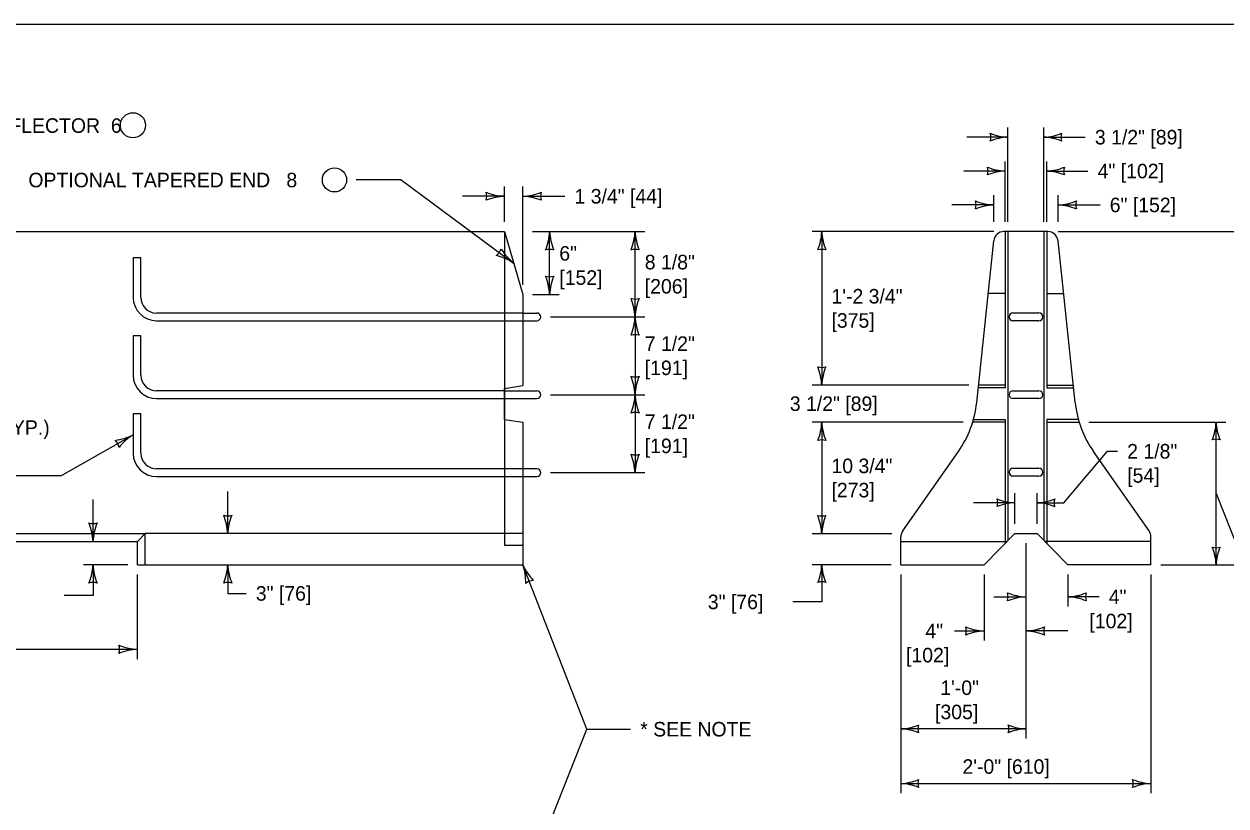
# Model space of a CAD drawing. Extents: x 49991.4 to 50021, y 49987.6 to 50011.4.
# Drawn here: x 50005.623 to 50010.586, y 49995.768 to 49998.999 of the extents above; entities that cross this region are included whole.
import ezdxf

# ---------------------------------------------------------------- set-up
doc = ezdxf.new("R2010")
doc.units = 0
for name, color, linetype in [('Level 1', 7, 'Continuous'), ('Level 2', 7, 'Continuous'), ('Level 3', 7, 'Continuous'), ('Level 4', 7, 'Continuous')]:
    doc.layers.add(name, color=color, linetype=linetype)

msp = doc.modelspace()

# ---------------------------------------------------------------- linework, layer by layer
at = {"layer": 'Level 1'}
for p, q in [((50002.518, 49998.1414), (50007.607, 49998.1414)), ((50007.607, 49998.1414), (50007.6828, 49997.8813)), ((50009.5572, 49997.4345), (50009.6279, 49998.1036)), ((50009.8515, 49998.1415), (50009.67, 49998.1415)), ((50009.6745, 49998.1415), (50009.6745, 49997.4963)), ((50009.686, 49998.1415), (50009.686, 49996.8645)), ((50009.8349, 49998.1415), (50009.8349, 49996.8645)), ((50009.8464, 49998.1415), (50009.8464, 49997.4963)), ((50009.9637, 49997.4345), (50009.893, 49998.1036)), ((50007.6828, 49997.8813), (50007.6829, 49997.5051)), ((50009.6745, 49997.8858), (50009.6049, 49997.8858)), ((50009.8464, 49997.8858), (50009.916, 49997.8858)), ((50007.6829, 49997.8049), (50007.7407, 49997.8049)), ((50009.7069, 49997.8052), (50009.8143, 49997.8052)), ((50007.6829, 49997.7728), (50007.7407, 49997.7728)), ((50009.8143, 49997.773), (50009.7069, 49997.773)), ((50007.6078, 49997.4932), (50007.6829, 49997.5051)), ((50009.6745, 49997.5069), (50009.5648, 49997.5069)), ((50009.8464, 49997.5069), (50009.9561, 49997.5069)), ((50007.6078, 49997.3655), (50007.6078, 49997.4932)), ((50007.6078, 49997.4833), (50007.7407, 49997.4833)), ((50009.6745, 49997.4963), (50009.5637, 49997.4963)), ((50009.7069, 49997.4835), (50009.8143, 49997.4835)), ((50009.8464, 49997.4963), (50009.9572, 49997.4963)), ((50007.6078, 49997.4512), (50007.7407, 49997.4512)), ((50009.8143, 49997.4513), (50009.7069, 49997.4513)), ((50007.6078, 49997.3655), (50007.6829, 49997.3535)), ((50009.544, 49997.3649), (50009.6745, 49997.3649)), ((50009.6745, 49997.3649), (50009.6745, 49996.8528)), ((50009.8464, 49997.3649), (50009.8464, 49996.8528)), ((50009.9769, 49997.3649), (50009.8464, 49997.3649)), ((50007.6829, 49997.3535), (50007.6829, 49996.7646)), ((50009.6745, 49997.3536), (50009.5407, 49997.3536)), ((50009.8464, 49997.3536), (50009.9802, 49997.3536)), ((50009.2517, 49996.9042), (50009.4814, 49997.232)), ((50010.2692, 49996.9042), (50010.0395, 49997.232)), ((50007.7408, 49997.1611), (50007.6829, 49997.161)), ((50009.7069, 49997.163), (50009.8143, 49997.163)), ((50007.6829, 49997.1289), (50007.7407, 49997.129)), ((50009.8143, 49997.1308), (50009.7069, 49997.1308)), ((50004.0777, 49996.8932), (50006.1232, 49996.8932)), ((50004.1097, 49996.8611), (50006.0912, 49996.8611)), ((50006.1232, 49996.8932), (50006.0912, 49996.8611)), ((50006.0912, 49996.7646), (50006.0912, 49996.8611)), ((50006.1232, 49996.7646), (50006.1232, 49996.8932)), ((50009.244, 49996.7646), (50009.244, 49996.8799)), ((50009.5877, 49996.7646), (50009.7144, 49996.8933)), ((50009.7144, 49996.8933), (50009.8065, 49996.8933)), ((50009.9332, 49996.7646), (50009.8065, 49996.8933)), ((50010.2769, 49996.7646), (50010.2769, 49996.8799)), ((50006.0912, 49996.7646), (50007.6829, 49996.7646)), ((50009.244, 49996.7646), (50009.5877, 49996.7646)), ((50010.2769, 49996.7646), (50009.9332, 49996.7646))]:
    msp.add_line(p, q, dxfattribs=at)
msp.add_lwpolyline([(49999.3835, 49998.9992), (50016.7501, 49998.9992), (50016.7501, 49987.7988), (49999.3835, 49987.7988)], close=True, dxfattribs=at)
for centre, radius, start, end in [((50009.67, 49998.0991), 0.0423, 90, 173.9725), ((50009.8509, 49998.0991), 0.0423, 6.0275, 90), ((50007.7407, 49997.7888), 0.0161, 270, 90), ((50009.7069, 49997.7891), 0.0161, 90, 270), ((50009.8143, 49997.7891), 0.0161, 270, 90), ((50007.7407, 49997.4673), 0.0161, 270, 90), ((50009.7069, 49997.4674), 0.0161, 90, 270), ((50009.8143, 49997.4674), 0.0161, 270, 90), ((50009.1277, 49997.4798), 0.4318, 324.9777, 353.9725), ((50010.3932, 49997.4798), 0.4318, 186.0275, 215.0223), ((50007.7407, 49997.1451), 0.0161, 270.1368, 89.5016), ((50009.7069, 49997.1469), 0.0161, 90, 270), ((50009.8143, 49997.1469), 0.0161, 270, 90), ((50009.2863, 49996.8799), 0.0423, 144.9777, 180), ((50010.2346, 49996.8799), 0.0423, 0, 35.0223)]:
    msp.add_arc(centre, radius, start, end, dxfattribs=at)
at = {"layer": 'Level 2'}
for centre, radius in [((50006.0727, 49998.5808), 0.052), ((50006.905, 49998.355), 0.05)]:
    msp.add_circle(centre, radius, dxfattribs=at)
at = {"layer": 'Level 3'}
for p, q in [((50009.686, 49998.1815), (50009.686, 49998.5716)), ((50009.8349, 49998.1815), (50009.8349, 49998.5716)), ((50009.686, 49998.5316), (50009.5157, 49998.5316)), ((50009.8349, 49998.5316), (50010.0052, 49998.5316)), ((50009.6745, 49998.1815), (50009.6745, 49998.4316)), ((50009.8464, 49998.1815), (50009.8464, 49998.4316)), ((50007.1798, 49998.355), (50006.995, 49998.355)), ((50007.1798, 49998.355), (50007.6449, 49998.0114)), ((50009.6745, 49998.3916), (50009.5042, 49998.3916)), ((50009.8464, 49998.3916), (50010.0167, 49998.3916)), ((50007.607, 49998.1814), (50007.607, 49998.3274)), ((50007.6828, 49997.9213), (50007.6828, 49998.3274)), ((50007.607, 49998.2874), (50007.4336, 49998.2874)), ((50007.6828, 49998.2874), (50007.8563, 49998.2874)), ((50009.6279, 49998.2516), (50009.4544, 49998.2516)), ((50009.6279, 49998.1815), (50009.6279, 49998.2916)), ((50009.893, 49998.1815), (50009.893, 49998.2916)), ((50009.893, 49998.2516), (50010.0665, 49998.2516)), ((50007.7228, 49998.1414), (50008.1864, 49998.1414)), ((50007.7934, 49997.8813), (50007.7934, 49998.1414)), ((50008.1464, 49997.7888), (50008.1464, 49998.1414)), ((50009.6279, 49998.1415), (50008.8774, 49998.1415)), ((50008.9174, 49998.1415), (50008.9174, 49997.5069)), ((50009.893, 49998.1415), (50011.0526, 49998.1415)), ((50007.7228, 49997.8813), (50007.8334, 49997.8813)), ((50007.7967, 49997.7888), (50008.1864, 49997.7888)), ((50008.1464, 49997.7888), (50008.1464, 49997.4673)), ((50009.5248, 49997.5069), (50008.8774, 49997.5069)), ((50007.7967, 49997.4673), (50008.1864, 49997.4673)), ((50008.1464, 49997.4673), (50008.1464, 49997.1451)), ((50009.5007, 49997.3536), (50008.8774, 49997.3536)), ((50008.9174, 49997.3536), (50008.9174, 49996.8926)), ((50010.0202, 49997.3536), (50010.5858, 49997.3536)), ((50010.5458, 49996.7646), (50010.5458, 49997.3536)), ((50005.7745, 49997.1316), (50006.0737, 49997.3016)), ((50005.7745, 49997.1316), (50005.4716, 49997.1316)), ((50007.7967, 49997.1451), (50008.1864, 49997.1451)), ((50006.4644, 49996.8932), (50006.4644, 49997.0666)), ((50009.7144, 49996.9333), (50009.7144, 49997.0607)), ((50009.8065, 49996.9333), (50009.8065, 49997.0607)), ((50005.9079, 49996.8611), (50005.9079, 49997.0345)), ((50009.7144, 49997.0207), (50009.5441, 49997.0207)), ((50009.8065, 49997.0207), (50009.9168, 49997.0207)), ((50009.206, 49996.8926), (50008.8774, 49996.8926)), ((50009.7605, 49996.8533), (50009.7605, 49996.0463)), ((50006.0512, 49996.7646), (50005.8679, 49996.7646)), ((50005.9079, 49996.7646), (50005.9079, 49996.6375)), ((50007.9477, 49996.0849), (50007.6829, 49996.7646)), ((50009.204, 49996.7646), (50008.8774, 49996.7646)), ((50008.9174, 49996.7646), (50008.9174, 49996.611)), ((50010.3169, 49996.7646), (50010.6227, 49996.7646)), ((50006.0912, 49996.375), (50006.0912, 49996.7246)), ((50009.244, 49996.7246), (50009.244, 49995.8204)), ((50009.5877, 49996.7246), (50009.5877, 49996.4509)), ((50009.9332, 49996.7246), (50009.9332, 49996.5919)), ((50010.2769, 49996.7246), (50010.2769, 49995.8205)), ((50005.9079, 49996.6375), (50005.7886, 49996.6375)), ((50009.6277, 49996.6319), (50009.7605, 49996.6319)), ((50010.0625, 49996.6319), (50009.9332, 49996.6319)), ((50008.9174, 49996.611), (50008.7979, 49996.611)), ((50009.4659, 49996.491), (50009.5877, 49996.491)), ((50009.9339, 49996.491), (50009.7605, 49996.491)), ((50004.1097, 49996.415), (50006.0912, 49996.415)), ((50007.6787, 49995.4076), (50007.9477, 49996.0849)), ((50007.9477, 49996.0849), (50008.1276, 49996.0849)), ((50009.7605, 49996.0863), (50009.244, 49996.0863)), ((50009.2439, 49995.8605), (50010.2769, 49995.8605))]:
    msp.add_line(p, q, dxfattribs=at)
for points in [[(50009.9168, 49997.0207), (50010.0976, 49997.2336), (50010.1386, 49997.2336)], [(50010.5458, 49997.0591), (50010.7677, 49996.4999), (50010.8466, 49996.4999)], [(50006.4644, 49996.7646), (50006.4644, 49996.6461), (50006.5401, 49996.6461)]]:
    msp.add_lwpolyline(points, dxfattribs=at)
for centre, radius, start, end in [((50009.6948, 49998.7442), 0.2128, 247.456, 267.6395), ((50009.5633, 49998.5316), 0.0524, 342.1388, 17.8612), ((50009.8261, 49998.7442), 0.2128, 272.3605, 292.544), ((50009.9576, 49998.5316), 0.0524, 162.1388, 197.8612), ((50009.697, 49998.3088), 0.2231, 92.8273, 112.0772), ((50009.8239, 49998.3088), 0.2231, 67.9228, 87.1727), ((50009.6833, 49998.6042), 0.2128, 247.456, 267.6395), ((50009.5518, 49998.3916), 0.0524, 342.1388, 17.8612), ((50009.8376, 49998.6042), 0.2128, 272.3605, 292.544), ((50009.9691, 49998.3916), 0.0524, 162.1388, 197.8612), ((50009.6855, 49998.1688), 0.2231, 92.8273, 112.0772), ((50009.8354, 49998.1688), 0.2231, 67.9228, 87.1727), ((50007.6162, 49998.5095), 0.2223, 247.456, 267.6395), ((50007.4788, 49998.2874), 0.0548, 342.1388, 17.8612), ((50007.6713, 49998.5201), 0.233, 272.8273, 292.0772), ((50007.8111, 49998.2874), 0.0548, 162.1388, 197.8612), ((50007.6185, 49998.0547), 0.233, 92.8273, 112.0772), ((50007.6737, 49998.0653), 0.2223, 67.456, 87.6395), ((50009.637, 49998.4737), 0.2223, 247.456, 267.6395), ((50009.4997, 49998.2516), 0.0548, 342.1388, 17.8612), ((50009.6394, 49998.0188), 0.233, 92.8273, 112.0772), ((50009.8839, 49998.4737), 0.2223, 272.3605, 292.544), ((50009.8815, 49998.0188), 0.233, 67.9228, 87.1727), ((50010.0212, 49998.2516), 0.0548, 162.1388, 197.8612), ((50007.5712, 49998.1505), 0.2223, 337.456, 357.6395), ((50008.0261, 49998.1529), 0.233, 182.8273, 202.0772), ((50007.9243, 49998.1505), 0.2223, 337.456, 357.6395), ((50008.3791, 49998.1529), 0.233, 182.8273, 202.0772), ((50008.6953, 49998.1506), 0.2223, 337.456, 357.6395), ((50009.1501, 49998.1529), 0.233, 182.8273, 202.0772), ((50007.5409, 49998.0862), 0.0548, 306.4104, 342.1327), ((50007.7821, 49998.1863), 0.2223, 211.7276, 231.9111), ((50007.7934, 49998.0132), 0.0548, 72.1388, 107.8612), ((50008.1464, 49998.0132), 0.0548, 72.1388, 107.8612), ((50008.9174, 49998.0132), 0.0548, 72.1388, 107.8612), ((50007.5184, 49997.8157), 0.233, 57.0989, 76.3487), ((50007.7934, 49998.0095), 0.0548, 252.1388, 287.8612), ((50007.5606, 49997.8698), 0.233, 2.8273, 22.0772), ((50008.0155, 49997.8722), 0.2223, 157.456, 177.6395), ((50008.1464, 49997.917), 0.0548, 252.1388, 287.8612), ((50007.9137, 49997.7773), 0.233, 2.8273, 22.0772), ((50008.3686, 49997.7797), 0.2223, 157.456, 177.6395), ((50007.9243, 49997.798), 0.2223, 337.456, 357.6395), ((50008.3791, 49997.8003), 0.233, 182.8273, 202.0772), ((50008.1464, 49997.6606), 0.0548, 72.1388, 107.8612), ((50008.9174, 49997.6351), 0.0548, 252.1388, 287.8612), ((50008.6847, 49997.4954), 0.233, 2.8273, 22.0772), ((50009.1395, 49997.4977), 0.2223, 157.456, 177.6395), ((50008.1464, 49997.5955), 0.0548, 252.1388, 287.8612), ((50007.9137, 49997.4558), 0.233, 2.8273, 22.0772), ((50008.3686, 49997.4581), 0.2223, 157.456, 177.6395), ((50007.9243, 49997.4764), 0.2223, 337.456, 357.6395), ((50008.3791, 49997.4788), 0.233, 182.8273, 202.0772), ((50008.1464, 49997.3391), 0.0548, 72.1388, 107.8612), ((50008.6953, 49997.3628), 0.2223, 337.456, 357.6395), ((50009.1501, 49997.3651), 0.233, 182.8273, 202.0772), ((50010.3331, 49997.3624), 0.2128, 337.456, 357.6395), ((50010.7686, 49997.3646), 0.2231, 182.8273, 202.0772), ((50005.9687, 49997.5096), 0.233, 277.5284, 296.7783), ((50005.9622, 49997.2383), 0.0548, 11.7444, 47.4668), ((50006.1914, 49997.113), 0.2223, 121.9661, 142.1496), ((50008.9174, 49997.2254), 0.0548, 72.1388, 107.8612), ((50010.5458, 49997.2309), 0.0524, 72.1388, 107.8612), ((50008.1464, 49997.2733), 0.0548, 252.1388, 287.8612), ((50007.9137, 49997.1336), 0.233, 2.8273, 22.0772), ((50008.3686, 49997.1359), 0.2223, 157.456, 177.6395), ((50009.7232, 49997.2333), 0.2128, 247.456, 267.6395), ((50009.5917, 49997.0207), 0.0524, 342.1388, 17.8612), ((50009.7254, 49996.7979), 0.2231, 92.8273, 112.0772), ((50009.7955, 49997.2435), 0.2231, 272.8273, 292.0772), ((50009.7977, 49996.808), 0.2128, 67.456, 87.6395), ((50009.9292, 49997.0207), 0.0524, 162.1388, 197.8612), ((50006.4644, 49997.0214), 0.0548, 252.1388, 287.8612), ((50006.2316, 49996.8817), 0.233, 2.8273, 22.0772), ((50006.6865, 49996.884), 0.2223, 157.456, 177.6395), ((50008.9174, 49997.0209), 0.0548, 252.1388, 287.8612), ((50008.6847, 49996.8811), 0.233, 2.8273, 22.0772), ((50009.1395, 49996.8835), 0.2223, 157.456, 177.6395), ((50005.9079, 49996.9893), 0.0548, 252.1388, 287.8612), ((50005.6752, 49996.8496), 0.233, 2.8273, 22.0772), ((50006.1301, 49996.8519), 0.2223, 157.456, 177.6395), ((50010.5459, 49996.8873), 0.0524, 252.1388, 287.8612), ((50010.3231, 49996.7536), 0.2231, 2.8273, 22.0772), ((50010.7586, 49996.7558), 0.2128, 157.456, 177.6395), ((50005.6858, 49996.7737), 0.2223, 337.456, 357.6395), ((50006.1406, 49996.7761), 0.233, 182.8273, 202.0772), ((50006.2422, 49996.7738), 0.2223, 337.456, 357.6395), ((50006.6971, 49996.7761), 0.233, 182.8273, 202.0772), ((50007.4726, 49996.6925), 0.2223, 358.7398, 18.9233), ((50007.8956, 49996.8598), 0.233, 204.1111, 223.3609), ((50008.6946, 49996.7756), 0.2231, 337.9228, 357.1727), ((50009.1301, 49996.7734), 0.2128, 182.3605, 202.544), ((50005.9079, 49996.6364), 0.0548, 72.1388, 107.8612), ((50006.4644, 49996.6364), 0.0548, 72.1388, 107.8612), ((50007.7294, 49996.6451), 0.0548, 93.4226, 129.1449), ((50008.9174, 49996.6419), 0.0524, 72.1388, 107.8612), ((50009.7696, 49996.854), 0.2223, 247.456, 267.6395), ((50009.6322, 49996.6319), 0.0548, 342.1388, 17.8612), ((50009.7719, 49996.3991), 0.233, 92.8273, 112.0772), ((50009.9217, 49996.8646), 0.233, 272.8273, 292.0772), ((50009.924, 49996.4097), 0.2223, 67.456, 87.6395), ((50010.0614, 49996.6319), 0.0548, 162.1388, 197.8612), ((50009.5969, 49996.7131), 0.2223, 247.456, 267.6395), ((50009.4595, 49996.491), 0.0548, 342.1388, 17.8612), ((50009.5992, 49996.2583), 0.233, 92.8273, 112.0772), ((50009.749, 49996.7237), 0.233, 272.8273, 292.0772), ((50009.7513, 49996.2688), 0.2223, 67.456, 87.6395), ((50009.8887, 49996.491), 0.0548, 162.1388, 197.8612), ((50006.1004, 49996.6371), 0.2223, 247.456, 267.6395), ((50005.963, 49996.415), 0.0548, 342.1388, 17.8612), ((50006.1027, 49996.1823), 0.233, 92.8273, 112.0772), ((50009.233, 49996.309), 0.2231, 272.8273, 292.0772), ((50009.2352, 49995.8736), 0.2128, 67.456, 87.6395), ((50009.3667, 49996.0863), 0.0524, 162.1388, 197.8612), ((50009.7692, 49996.299), 0.2128, 247.456, 267.6395), ((50009.6377, 49996.0863), 0.0524, 342.1388, 17.8612), ((50009.7715, 49995.8635), 0.2231, 92.8273, 112.0772), ((50009.233, 49996.0833), 0.2231, 272.8273, 292.0772), ((50009.3667, 49995.8605), 0.0524, 162.1388, 197.8612), ((50010.2861, 49996.0826), 0.2223, 247.456, 267.6395), ((50010.1487, 49995.8605), 0.0548, 342.1388, 17.8612), ((50009.2352, 49995.6478), 0.2128, 67.456, 87.6395), ((50010.2884, 49995.6278), 0.233, 92.8273, 112.0772)]:
    msp.add_arc(centre, radius, start, end, dxfattribs=at)
at = {"layer": 'Level 4'}
for p, q in [((50007.6078, 49998.1388), (50007.6078, 49996.845)), ((50006.1057, 49998.0328), (50006.0736, 49998.0328)), ((50006.0736, 49998.0328), (50006.0736, 49997.8689)), ((50006.1057, 49997.8689), (50006.1057, 49998.0328)), ((50007.6829, 49997.8049), (50006.1698, 49997.8049)), ((50006.1698, 49997.7728), (50007.6829, 49997.7728)), ((50006.1058, 49997.7112), (50006.0737, 49997.7112)), ((50006.0737, 49997.7112), (50006.0737, 49997.5474)), ((50006.1058, 49997.5474), (50006.1058, 49997.7112)), ((50007.6078, 49997.4833), (50006.1699, 49997.4833)), ((50006.1699, 49997.4512), (50007.6078, 49997.4512)), ((50006.1058, 49997.3889), (50006.0737, 49997.3889)), ((50006.0737, 49997.3889), (50006.0737, 49997.225)), ((50006.1058, 49997.225), (50006.1058, 49997.3889)), ((50007.6829, 49997.161), (50006.1699, 49997.161)), ((50006.1699, 49997.1289), (50007.6829, 49997.1289)), ((50007.6829, 49996.8932), (50006.1232, 49996.8932)), ((50009.244, 49996.8611), (50009.6827, 49996.8611)), ((50010.2769, 49996.8611), (50009.8382, 49996.8611)), ((50007.6078, 49996.845), (50007.6829, 49996.845))]:
    msp.add_line(p, q, dxfattribs=at)
for centre, radius, start, end in [((50006.1704, 49997.8696), 0.0969, 180.4343, 269.6039), ((50006.1698, 49997.8689), 0.064, 180, 270), ((50006.1705, 49997.5481), 0.0969, 180.4343, 269.6039), ((50006.1699, 49997.5474), 0.064, 180, 270), ((50006.1705, 49997.2257), 0.0969, 180.4343, 269.6039), ((50006.1699, 49997.225), 0.064, 180, 270)]:
    msp.add_arc(centre, radius, start, end, dxfattribs=at)

# ---------------------------------------------------------------- texts
at = {"layer": 'Level 2'}
for s, p in [('REFLECTOR  6', (50005.451, 49998.5495)), ('3 1/2" [89]', (50010.0452, 49998.5016)), ('4" [102]', (50010.0567, 49998.3616)), ('OPTIONAL TAPERED END   8', (50005.6409, 49998.3245)), ('1 3/4" [44]', (50007.8963, 49998.2574)), ('6" [152]', (50010.1065, 49998.2216)), ('6"', (50007.8334, 49998.0213)), ('8 1/8"', (50008.1864, 49997.9853)), ('[152]', (50007.8334, 49997.9213)), ('[206]', (50008.1864, 49997.8853)), ('1\'-2 3/4"', (50008.9574, 49997.8442)), ('[375]', (50008.9574, 49997.7442)), ('7 1/2"', (50008.1864, 49997.6483)), ('[191]', (50008.1864, 49997.5483)), ('3 1/2" [89]', (50008.7853, 49997.4002)), ('OPTIONAL LOOP (TYP.)', (50004.824, 49997.3016)), ('7 1/2"', (50008.1864, 49997.3257)), ('[191]', (50008.1864, 49997.2257)), ('2 1/8"', (50010.1786, 49997.2036)), ('10 3/4"', (50008.9574, 49997.1431)), ('[54]', (50010.1786, 49997.1036)), ('[273]', (50008.9574, 49997.0431)), ('3" [76]', (50006.5801, 49996.6161)), ('4"', (50010.1025, 49996.6019)), ('3" [76]', (50008.4468, 49996.581)), ('[102]', (50010.0226, 49996.5019)), ('4"', (50009.3452, 49996.461)), ('[102]', (50009.2653, 49996.361)), ('1\'-0"', (50009.4068, 49996.2263)), ('[305]', (50009.3851, 49996.1263)), ('* SEE NOTE', (50008.1676, 49996.0549)), ('2\'-0" [610]', (50009.4983, 49995.9005))]:
    msp.add_text(s, height=0.06, dxfattribs=at).set_placement(p)

doc.saveas('drawing.dxf')
